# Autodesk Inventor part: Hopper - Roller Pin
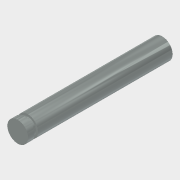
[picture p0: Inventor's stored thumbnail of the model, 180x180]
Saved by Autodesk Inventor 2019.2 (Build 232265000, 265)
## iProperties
Created: 2005-11
Part Number: Hopper - Roller Pin
Document SubType Name: Modeling
Designer: floress
Material: Default
Density: 1 g/cm^3
Appearance: Zinc
Author: floress
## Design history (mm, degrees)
sketch "Sketch1"
  geometry: C1 r 0.794 at (0, 0)
  constraints: 1 centre point
  dimensions: "d0" = 1.5875 diameter of C1
extrude "Extrusion1" new body sketch "Sketch1" distance "d1" = 10.31875; taper "d2" = 0 deg
sketch "Sketch2"
  geometry: C1 r 0.794 at (0, 0) reference; C2 r 0.635 at (0, 0)
  constraints: 1 centre point, 1 coincident
  dimensions: "d3" = 1.27 diameter of C2
extrude "Extrusion2" join sketch "Sketch2" distance "d4" = 0.254; taper "d5" = 0 deg
sketch "Sketch3"
  geometry: C1 r 0.635 at (0, 0) reference; C2 r 0.794 at (0, 0)
  constraints: 1 centre point, 1 coincident
  dimensions: "d6" = 1.5875 diameter of C2
extrude "Extrusion3" join sketch "Sketch3" distance "d7" = 0.508; taper "d8" = 0 deg
body "Solid1"
